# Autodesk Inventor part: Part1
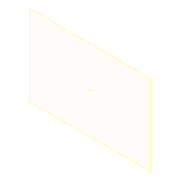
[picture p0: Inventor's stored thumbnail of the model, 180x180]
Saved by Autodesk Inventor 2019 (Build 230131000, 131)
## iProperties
Created: 2015-07
Part Number: Part1
Material: Generic
Document SubType Name: Modeling
Designer: Sandeep
Density: 1 g/cm^3
Appearance: Default
Author: Sandeep
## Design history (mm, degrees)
sketch "Sketch1"
  geometry: 1 further point
  constraints: 1 other
feature "Form1"
body "Srf1"
